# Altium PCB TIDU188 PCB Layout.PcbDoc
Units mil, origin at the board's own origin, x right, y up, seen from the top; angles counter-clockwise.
Board outline 3160 x 1390 mil, 4 copper layers (Top Layer, Ground, POWER, Bottom Layer), stack 90 mil thick; 74 components, 47 nets, 222 pads, 107 vias.
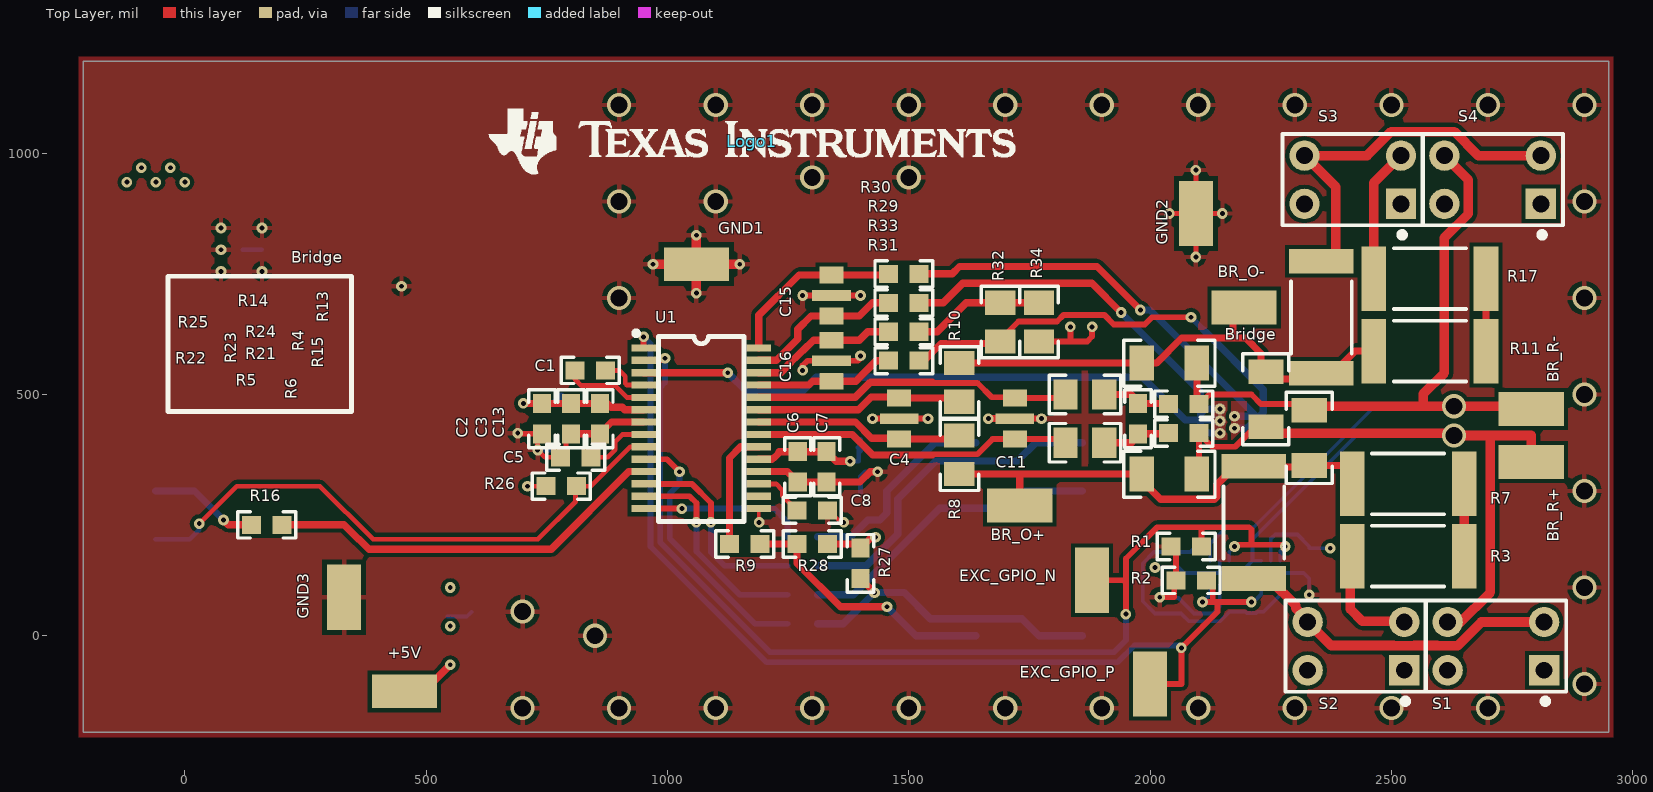
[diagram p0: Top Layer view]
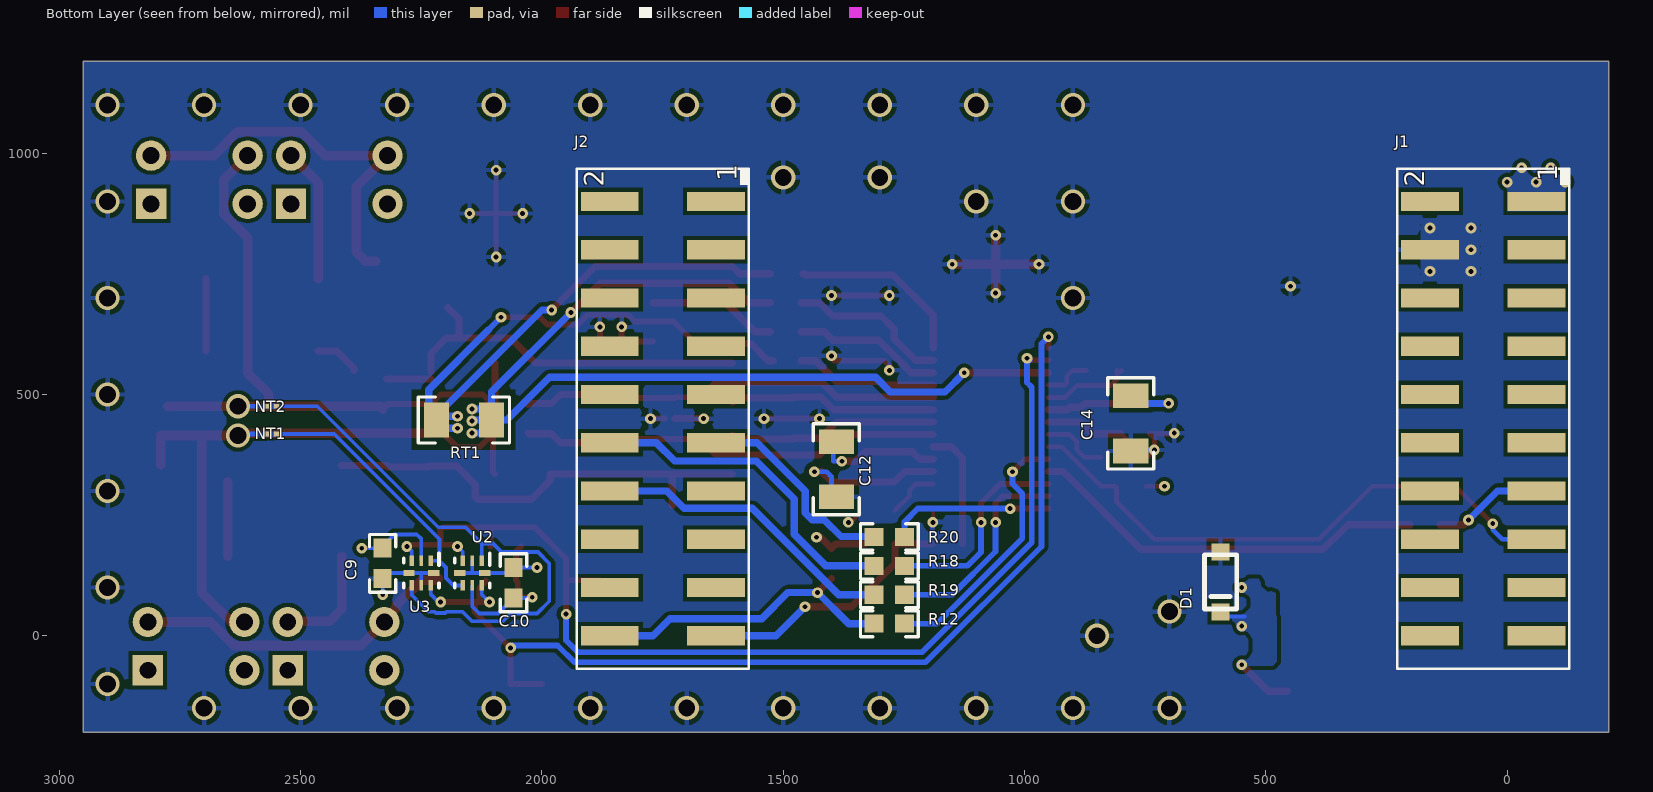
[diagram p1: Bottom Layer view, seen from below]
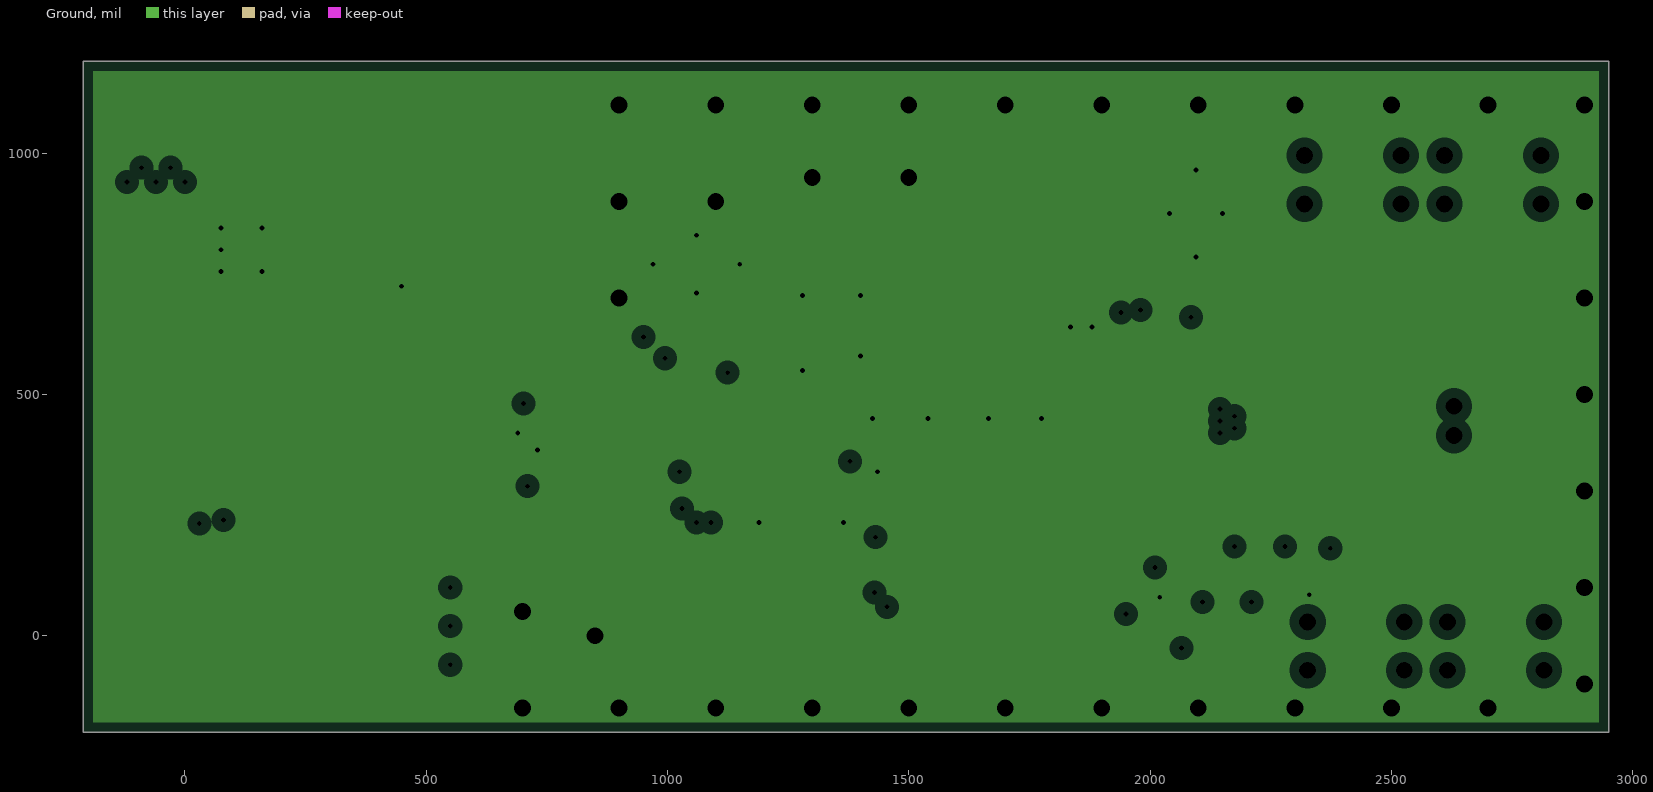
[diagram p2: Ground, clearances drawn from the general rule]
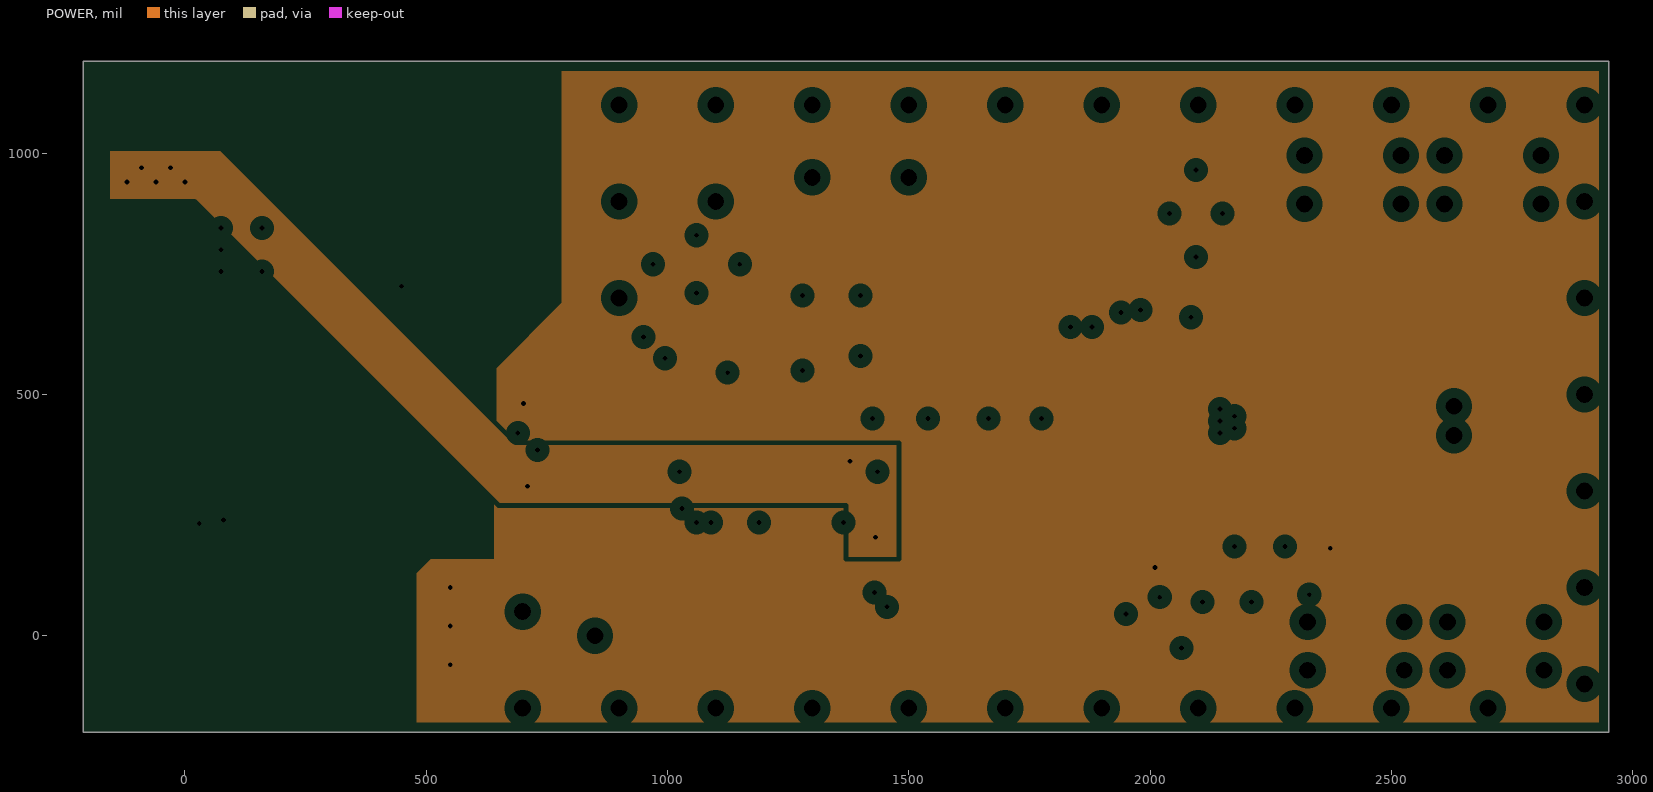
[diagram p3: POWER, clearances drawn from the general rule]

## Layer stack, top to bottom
Top Solder: solder mask 0.4, Solder Resist, Dk 3.5
Top Layer: signal copper 1.4
Dielectric1: core 59.2, FR-4, Dk 4.8
Ground: plane copper 1.4, net GND
Dielectric2: prepreg 12.6, FR-4, Dk 4.8
POWER: plane copper 1.4, net (Multiple Nets)
Dielectric3: core 12.6, FR-4, Dk 4.8
Bottom Layer: signal copper 1.4
Bottom Solder: solder mask 0.4, Solder Resist, Dk 3.5

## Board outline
-210,-200 2950,-200 2950,1190 -210,1190

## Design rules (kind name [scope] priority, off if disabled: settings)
AcuteAngle [All] p1: minimum=4.50000000000000E+0001 checktracksonly=FALSE
AssemblyTestPointUsage [All] p1: valid=2
Clearance Clearance_1 [InNet('NetJP1_1') OR InNet('GND') OR InNet('+3.3V') OR InNet('NetC16_2') OR InNet('NetC17_2') OR InNet('NetJ4_2') OR InNet('NetJ4_1') OR InNet('NetR21_1') OR InNet('NetR22_2') OR InNet('NetC32_2') OR InNet('-5V') OR InNet('+5V') OR InNet('NetJ1_7') OR InNet('NetJ1_6') OR InNet('NetJ1_13') OR InNet('NetJ1_11') OR InNet('NetR26_1') OR InNet('SDA') OR InNet('SCL') OR InNet('NetJ1_15') OR InNet('NetJ1_3') OR InNet('START') OR InNet('SCLK') OR InNet('DGND') OR NOT InAnyNet vs InNet('DGND')] p1 off: gap=10
Clearance GND_TIE [(InNet('GND') OR InNet('DGND'))] p2 off: gap=0
Clearance Clearance_BoardEdge_MountingHoles [OnCopper and InComponentClass('Mounting Holes') vs IsKeepOut] p3: gap=40
Clearance Clearance_BoardEdge_Poly [OnCopper and InPoly vs IsKeepOut] p4: gap=25
Clearance Clearance_BoardEdge [OnCopper and Not InComponentClass('Logo') and not InComponentClass('FiducialMark') and not InRegion(1000,500,4000,800) vs IsKeepOut] p5: gap=25
Clearance [All] p6: gap=8
ComponentClearance ComponentClearance_Logo [InComponentClass(Logo)] p1 off: gap=50 collisioncheckmode=3 verticalgap=10 showdistances=FALSE
ComponentClearance ComponentClearance_ScrewToNut [(HasFootprint('NY PMS 440 0025 PH')) vs (HasFootprint('Keystone_1902C'))] p2 off: gap=5 collisioncheckmode=3 verticalgap=10 showdistances=FALSE
ComponentClearance ComponentClearance_MountingHoles [InComponentClass('Mounting Holes')] p3 off: gap=250 collisioncheckmode=3 verticalgap=100000 showdistances=FALSE
ComponentClearance ComponentClearance_SmallPassives [HasFootprint('0201*') or HasFootprint('0402*') or HasFootprint('0508') or HasFootprint('0603*') or HasFootprint('0612') or HasFootprint('0805*') or HasFootprint('0815*') or HasFootprint('0830*') or HasFootprint('1206*') or HasFootprint('1210*') or HasFootprint('1808*') or HasFootprint('1812*') or HasFootprint('1825*') or HasFootprint('2010*') or HasFootprint('2220*') or HasFootprint('2225*') or HasFootprint('2512*') or HasFootprint('2728*') or HasFootprint('3518*') vs HasFootprint('0201*') or HasFootprint('0402*') or HasFootprint('0508') or HasFootprint('0603*') or HasFootprint('0612') or HasFootprint('0805*') or HasFootprint('0815*') or HasFootprint('0830*') or HasFootprint('1206*') or HasFootprint('1210*') or HasFootprint('1808*') or HasFootprint('1812*') or HasFootprint('1825*') or HasFootprint('2010*') or HasFootprint('2220*') or HasFootprint('2225*') or HasFootprint('2512*') or HasFootprint('2728*') or HasFootprint('3518*')] p4 off: gap=20 collisioncheckmode=3 verticalgap=10 showdistances=FALSE
ComponentClearance ComponentClearance_THtoSMT [IsThruComponent vs IsSMTComponent] p5 off: gap=100 collisioncheckmode=3 verticalgap=100000 showdistances=FALSE
ComponentClearance ComponentClearance_THtoTH [IsThruComponent vs IsThruComponent] p6 off: gap=118.11 collisioncheckmode=3 verticalgap=100000 showdistances=FALSE
ComponentClearance [All] p7 off: gap=40 collisioncheckmode=3 verticalgap=10 showdistances=FALSE
DiffPairsRouting [All] p1: maxlimit=100 minlimit=10 mostfreqgap=10 toplayer_minwidth=15 toplayer_maxwidth=15 toplayer_prefwidth=15 bottomlayer_minwidth=15 bottomlayer_maxwidth=15 bottomlayer_prefwidth=15 maxuncoupledlength=1000
FabricationTestPointUsage TestPointUsage [All] p1: valid=2 allowmultiple=FALSE
FabricationTestpoint Testpoint [All] p1: side=3 testpointundercomponent=TRUE minsize=40 maxsize=100 preferedsize=60 minholesize=0 maxholesize=40 preferedholesize=32 testpointgrid=1 allowsidetop=TRUE allowsidebottom=TRUE usegrid=TRUE gridtolerance=0.01
FanoutControl Fanout_LCC [IsLCC] p1: bgadir=Out bgaviamode=Centered fanoutstyle=Auto fanoutdirection=Alternating viagrid=1 // Fanout_LCC (Default Rule)
FanoutControl Fanout_BGA [IsBGA] p2: bgadir=Out bgaviamode=Centered fanoutstyle=Auto fanoutdirection=Alternating viagrid=1 // Fanout_BGA (Default Rule)
FanoutControl Fanout_Default [All] p4: bgadir=Out bgaviamode=Centered fanoutstyle=Auto fanoutdirection=Alternating viagrid=1 // Fanout_Default (Default Rule)
FanoutControl Fanout_Small [(CompPinCount < 5)] p5: bgadir=Out bgaviamode=Centered fanoutstyle=Auto fanoutdirection=OutThenIn viagrid=1 // Fanout_Small (Default Rule)
HoleSize [All] p1: absolutevalues=TRUE maxlimit=251 minlimit=8 maxpercent=80.000 minpercent=20.000
MatchedLengths [All] p1 off: tolerance=10 checknetsindiffpair=TRUE checkdiffpairvsdiffpair=TRUE checkothers=TRUE
MinimumAnnularRing [All] p1 off: minimumring=9
MinimumSolderMaskSliver MinimumSolderMaskSliver_Logo [InComponentClass('Logo') vs InComponentClass('Logo')] p1: minsoldermaskwidth=0.7
MinimumSolderMaskSliver [All] p2 off: minsoldermaskwidth=4
NetAntennae [All] p1: netantennaetolerance=-2
PlaneClearance [All] p1: clearance=20
PlaneConnect PlaneConnect_1 [InComponent('U301') or InNet('DVDD') or InComponent('U302')] p1: planeconnectstyle=Direct reliefexpansion=10 reliefentries=4 reliefconductorwidth=10 reliefairgap=6
PlaneConnect [All] p2: planeconnectstyle=Relief reliefexpansion=10 reliefentries=4 reliefconductorwidth=10 reliefairgap=10
PolygonConnect PowerPolygon [(ObjectKind = 'Poly') And ((Name = 'Boost_GND') Or (Name = 'Boost_OUT')Or (Name = 'Boost_IN')Or (Name = 'LDO_GND') Or (Name = 'LDO_IN') Or (Name = 'LDO_OUT') Or (Name = '+5V_Connector_B') Or (Name = '+5V_Connector_T')Or (Name = 'DVDD_PAD')Or (Name = 'GND_PAD')Or (Name = 'AINCOM_PL')Or (Name = 'NetR116_PL'))] p1: connectstyle=Direct reliefconductorwidth=10 reliefentries=2 polygonreliefangle="90 Angle" airgapwidth=10
PolygonConnect [All] p2: connectstyle=Relief reliefconductorwidth=10 reliefentries=4 polygonreliefangle="90 Angle" airgapwidth=10
RoutingVias [All] p1: holewidth=16 width=34 viastyle="Through Hole" minholewidth=8 minwidth=20 maxholewidth=40 maxwidth=65
SMDToCorner [All] p1: distance=30000
SilkToSilkClearance [All] p1: silktosilkclearance=5
SilkToSolderMaskClearance SilkscreenOverComponentPads [IsPad] p1 off: minsilkscreentomaskgap=5 clearancetoexposedcopper=TRUE
SolderMaskExpansion [All] p1: expansion=3
UnpouredPolygon [All] p1: allowunpoured=FALSE
Width [All] p1: maxlimit=100 minlimit=6 preferedwidth=10 checkconnectedcopper=TRUE
13 further rules are at their usual default settings.

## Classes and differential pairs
component class "TIDU188 Temp Sensor": C22 C23 R34 RT1

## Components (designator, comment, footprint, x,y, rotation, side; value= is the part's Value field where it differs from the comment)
+5V "5015" 5015 455,-115 r0 top
BR_O+ "5015" 5015 1730,270 r180 top
BR_O- "5015" 5015 2195,680 r180 top
BR_R+ "5015" 5015 2790,360 r180 top
BR_R- "5015" 5015 2790,470 r180 top
C1 "GRM188R71H472KA01D" 0603 840,550 r180 top
C2 "GRM185R61C105KE44D" 0603 740,450 r270 top
C3 "GRM188R71C104KA01D" 0603 800,450 r270 top
C4 "250X15W104MV4E" "X2Y 0805 (X15)" 1480,450 r180 top
C5 "GRM185R61C105KE44D" 0603 810,370 r180 top
C6 "GRM188R71C104KA01D" 0603 1270,350 r270 top
C7 "GRM185R61C105KE44D" 0603 1330,350 r270 top
C8 "GRM185R61C105KE44D" 0603 1300,260 r0 top
C9 "GRM185R61C105KE44D" 0603 2330,150 r90 bottom
C10 "GRM185R61C105KE44D" 0603 2058.82,110 r90 bottom
C11 "250X15W104MV4E" "X2Y 0805 (X15)" 1720,450 r180 top
C12 "C3216X7R1C106M" 1206 1390,345 r270 bottom
C13 "GRM188R71E103KA01D" 0603 860,450 r270 top
C14 "C3216X7R1C106M" 1206 780,440 r270 bottom
C15 "250X15W104MV4E" "X2Y 0805 (X15)" 1340,705 r180 top
C16 "250X15W104MV4E" "X2Y 0805 (X15)" 1340,570 r180 top
D1 "DDZ6V2B-7" SOD-123 593.86,111.66 r270 bottom
EXC_GPIO_N "5015" 5015 1880,115 r90 top
EXC_GPIO_P "5015" 5015 2000,-100 r90 top
GND1 "5015" 5015 1060,770 r180 top
GND2 "5015" 5015 2095,875 r270 top
GND3 "5015" 5015 330,80 r270 top
J1 "SSW-110-22-F-D-VS-K" CONN_SSW-110-22-F-D-VS-K 49.5,449.98 r90 bottom
J2 "SSW-110-22-F-D-VS-K" CONN_SSW-110-22-F-D-VS-K 1749.5,449.98 r90 bottom
Logo1 "Texas Instruments" TI_Horizontal_Overlay_Small 1175,1025 r0 top
NT1 "Net-Tie" Net-Tie_10mil 2560,417.91 r180 bottom net-tie
NT2 "Net-Tie" Net-Tie_10mil 2560,475.63 r0 bottom net-tie
R1 "ERJ-3GEYJ104V" 0603 2075,185 r180 top
R2 "ERJ-3GEYJ104V" 0603 2085,115 r180 top
R3 "804-2512" 2512 2535,165 r180 top
R4 "804-1206" 1206 2240,490 r270 top
R5 "804-1206" 1206 2040,335 r0 top
R6 "804-2512" 2512 2215,235 r270 top
R7 "804-2512" 2512 2535,315 r0 top
R8 "ERJ-3EKF47R0V" 0805_HV 1605,375 r90 top
R9 "ERJ-3EKF47R0V" 0603 1160,190 r0 top
R10 "ERJ-3EKF47R0V" 0805_HV 1605,525 r270 top
R11 "804-2512" 2512 2580,590 r180 top
R12 "ERJ-3EKF47R0V" 0603 1280,25 r0 bottom
R13 "804-2512" 2512 2355,660 r270 top
R14 "804-1206" 1206 2040,565 r180 top
R15 "804-1206" 1206 2330,410 r270 top
R16 "ERJ-3EKF47R0V" 0603 170,230 r180 top
R17 "804-2512" 2512 2580,740 r0 top
R18 "ERJ-3EKF47R0V" 0603 1280,145 r0 bottom
R19 "ERJ-3EKF47R0V" 0603 1280,85 r0 bottom
R20 "ERJ-3EKF47R0V" 0603 1280,205 r0 bottom
R21 "RG1608P-4990-B-T5" 0603 2070,420 r180 top
R22 "2-1879336-4" 0805_HV 1865,400 r180 top
R23 "RG1608P-9091-B-T5" 0603 1975,450 r270 top
R24 "RG1608P-4990-B-T5" 0603 2070,480 r180 top
R25 "2-1879336-4" 0805_HV 1865,500 r180 top
R26 "ERJ-3GEYJ104V" 0603 780,310 r0 top
R27 "ERJ-3GEYJ104V" 0603 1400,150 r270 top
R28 "ERJ-3GEYJ104V" 0603 1300,190 r0 top
R29 "RC0603FR-07499RL" 0603 1490,690 r180 top
R30 "RC0603FR-07499RL" 0603 1490,750 r180 top
R31 "RC0603FR-07499RL" 0603 1490,570 r180 top
R32 "RG2012P-102-B-T5" 0805_HV 1690,650 r270 top
R33 "RC0603FR-07499RL" 0603 1490,630 r180 top
R34 "RG2012P-102-B-T5" 0805_HV 1770,650 r90 top
RT1 "PTS120601B100RP100" 1206 2161.65,447.09 r180 bottom
S1 "200USP9T1A1M2RE" 200USP9xxxxM2 2716.65,-21.46 r180 top
S2 "200USP9T1A1M2RE" 200USP9xxxxM2 2426.65,-21.46 r180 top
S3 "200USP9T1A1M2RE" 200USP9xxxxM2 2420,945 r180 top
S4 "200USP9T1A1M2RE" 200USP9xxxxM2 2710,945 r180 top
U1 "ADS1263IPW" PW28 1070,430 r0 top
U2 "TS5A21366RSER" RSE-8 2144.41,130 r0 bottom
U3 "TS5A21366RSER" RSE-8 2250,130 r0 bottom

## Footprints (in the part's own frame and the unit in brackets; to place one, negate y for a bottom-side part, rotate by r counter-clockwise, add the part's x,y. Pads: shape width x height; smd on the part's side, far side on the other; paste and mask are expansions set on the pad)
200USP9xxxxM2 [mm] "E-SWITCH"
  rect 1.6x1.6 hole 0.889: 1(-2.54,1.27)
  round 1.6 hole 0.889: 3(2.54,1.27) 4(-2.54,-1.27) 6(2.54,-1.27)
  silkscreen extent -3.7,-2.4 3.7,3.05, body extent -3.5,-2.25 3.5,2.25, height 11.12
0603 [mm] "0603 from SM-752 data"
  rect 1x0.95 smd: 1(-0.8,0) 2(0.8,0)
  silkscreen extent -1.52,-0.69 1.52,0.69, body extent -0.87,-0.47 0.87,0.47, height 0.85
0805_HV [mil] "0805 with 30mil clearance between pads"
  rect 50x63 smd: 1(-40,0) 2(40,0)
  silkscreen extent -74,-40 74,40, body extent -43,-29 43,29, height 43
1206 [mm] "1206 from SM-752 data"
  rect 1.3x1.85 smd: 1(-1.45,0) 2(1.45,0)
  silkscreen extent -2.4,-1.21 2.4,1.21, body extent -1.7,-0.9 1.7,0.9, height 1.35
2512 [mm] "Chip Resistor, Body 6.3x3.2mm, IPC Medium Density"
  rect 1.3x3.4 smd: 1(-2.95,0) 2(2.95,0)
  silkscreen extent -1.9,-1.6 1.9,1.6, body extent -3.22,-1.67 3.22,1.67, height 0.71
5015 [mil]
  rect 135x70 smd: 1(0,0)
CONN_SSW-110-22-F-D-VS-K [mil]
  rect 40x120 smd: 1(450,-110) 2(450,110) 3(350,-110) 4(350,110) 5(250,-110) 6(250,110) 7(150,-110) 8(150,110) 9(50,-110) 10(50,110) 11(-50,-110) 12(-50,110) 13(-150,-110) 14(-150,110) 15(-250,-110) 16(-250,110) 17(-350,-110) 18(-350,110) 19(-450,-110) 20(-450,110)
  silkscreen extent -518,-178 518,178, body extent -510,-155 500,155, height 435
Net-Tie_10mil [mil] "10mil net tie, no solder mask opening, no solder paste"
  rect 10x10 smd paste-5 mask-5: 1(-10,0) 2(10,0)
  Top Layer region: -6,5 6,5 6,-5 -6,-5
PW28 [mil]
  rect 50.31x15 smd: 1(-119.34,166.4) 2(-119.34,140.8) 3(-119.34,115.2) 4(-119.34,89.6) 5(-119.34,64) 6(-119.34,38.4) 7(-119.34,12.8) 8(-119.34,-12.8) 9(-119.34,-38.4) 10(-119.34,-64) 11(-119.34,-89.6) 12(-119.34,-115.2) 13(-119.34,-140.8) 14(-119.34,-166.4) 15(119.34,-166.4) 16(119.34,-140.8) 17(119.34,-115.2) 18(119.34,-89.6) 19(119.34,-64) 20(119.34,-38.4) 21(119.34,-12.8) 22(119.34,12.8) 23(119.34,38.4) 24(119.34,64.1) 25(119.34,89.6) 26(119.34,115.2) 27(119.34,140.8) 28(119.34,166.5)
  silkscreen extent -140,-193 89,202
RSE-8 [mm]
  rect 0.25x0.55 smd: 1(-0.5,-0.65) 3(0.5,-0.65) 5(0.5,0.65) 7(-0.5,0.65)
  rect 0.2x0.55 smd: 2(0,-0.65) 6(0,0.65)
  rect 0.6x0.3 smd: 4(0.65,0) 8(-0.65,0)
  silkscreen extent -0.92,-1.02 0.92,0.77
SOD-123 [mm]
  rect 0.9x0.95 smd: 1(-1.575,0) 2(1.575,0)
  silkscreen extent -1.43,-0.85 1.43,0.85, body extent -1.43,-0.85 1.43,0.85, height 1.36
TI_Horizontal_Overlay_Small [mil]
  silkscreen extent -545,-68 545,67
"X2Y 0805 (X15)" [mil]
  rect 50x35 smd: A(0,42.5) B(0,-42.5)
  rect 80x22 smd: G(0,0)

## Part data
+5V BR_O+ BR_O- BR_R+ BR_R- EXC_GPIO_N EXC_GPIO_P GND1 GND2 GND3: library part "Test Point SMT", "TEST POINT, MINIATURE, SMT"
C1: library part Cap_small, "CAP, CERM, 4700pF, 50V, +/-10%, X7R, 0603"
C2 C5 C7 C8 C9 C10: library part Cap_small, "CAP, CERM, 1uF, 16V, +/-10%, X5R, 0603"
C3 C6: library part Cap_small, "CAP, CERM, 0.1uF, 16V, +/-10%, X7R, 0603"
C4 C11 C15 C16: library part CAP_X2Y, "CAP, CERM X2Y, 100 nF, 25V, X7R, +/-20%, 0805"
C12: library part Cap_small, "CAP, CERM, 10 uF, 16V, X7R +/-20%, 1206"
C13: "CAP, CERM, 0.01uF, 25V, +/-10%, X7R, 0603"
C14: library part Capacitor, "CAP, CERM, 10 uF, 16V,  X7R +/-20%, 1206"
D1: library part "Zener Diode", "DIODE, ZENER, 6.2V, 500mW, SOD-123"
J1 J2: "Connector, Receptacle, 100mil, 10x2, Gold plated, SMD"
Logo1: library part TI_Logo, "Texas Instrument Corporate Signature"
NT1 NT2: "Single point connection between nets."
R1 R2 R26: library part Resistor_small, "RES, 100k Ohm, 5%, 1/10W, 0603"
R3 R6 R11 R13: library part Resistor_small, "RES, 87.325k Ohm, 0.01%, 0.75W, 2512"
R4 R5 R14 R15: library part Resistor_small, "RES, 350 ohm, 0.25%, 0.3W, 1206"
R7: library part Resistor_small, "RES, 87.5 kohm, 0.5%, 0.75W, 2512"
R8 R9 R10 R12 R16 R18 R19 R20 R22 R25: library part Resistor, "RES, 47 Ohm, 1%, 1/10W, 0603"
R17: library part Resistor_small, "RES, 87.5k Ohm, 0.5%, 0.75W, 2512"
R21 R24: "RES, 499 ohm, 0.1%, 0.1W, 0603"
R23: "RES, 9.09k ohm, 0.1%, 0.1W, 0603"
R27 R28: library part Resistor, "RES, 100k Ohm, 5%, 1/10W, 0603"
R29 R30 R31 R33: "RES, 499 ohm, 1%, 0.1W, 0603"
R32 R34: "RES, 1.00k ohm, 0.1%, 0.125W, 0805"
RT1: "Temperature Sensor, 100 ohm, 1%, 1206"
S1 S2 S3 S4: "Switch, Toggle, SPST, 1Pos, TH"
U1: library part ADS126XPW, "IC, 32-bit, 38kSPS ADC"
U2 U3: library part TS5A21366RSE, "IC, Single-Channel 10 Ohms SPDT Analog Switch with enable"

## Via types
v1: diameter 22, hole 10, Top Layer to Bottom Layer, 70 vias
v2: diameter 50, hole 35, Top Layer to Bottom Layer, 37 vias

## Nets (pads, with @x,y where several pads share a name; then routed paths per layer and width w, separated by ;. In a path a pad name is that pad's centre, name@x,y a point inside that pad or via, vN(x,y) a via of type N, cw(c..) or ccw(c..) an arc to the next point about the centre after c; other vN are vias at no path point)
\CS: J2.20 R12.2 R27.2 | length 652.8
  Top Layer w15: R27.2 v1(1428.96,89.54)
  Bottom Layer w15: R12.2 1364.42,25 v1(1428.96,89.54) 1490.46,89.54 1544.52,35.48 1734.52,35.48 1770.02,-0.02 J2.20
\DRDY: J2.11 R20.2 | length 435.5
  Bottom Layer w15: R20.2 1312.08,205.58 1380.58,205.58 1415,240 1440,240 1454.42,254.42 1454.42,300.04 1554.36,399.98 J2.11
\RESET/PWDN: J2.19 R9.2 R28.1 | length 550.1
  Top Layer w15: R9.2 R28.1 1268.5,150 1358.5,60 v1(1455,60)
  Bottom Layer w15: v1(1455,60) 1515.02,-0.02 J2.19
AIN0: C11.A R22.2 U1.21 | length 683
  Top Layer w12: 1550,376 1642.3,376 1673.8,407.5 1725,407.5 1832.5,407.5 R22.2@1840,400
  Top Layer w15: U1.21 1382.8,417.2 1425.5,374.5 1548.5,374.5
AIN1: C4.A R8.2 U1.22 | length 432.6
  Top Layer w15: U1.22 1389.73,442.8 1423.03,409.5 C4.A@1480,409.5 ; C4.A 1597.5,407.5 R8.2
AIN2: C4.B R10.2 U1.23 | length 429.8
  Top Layer w15: U1.23 1395.93,468.4 1422.47,494.95 C4.B@1480,494.95 ; C4.B 1597.5,492.5 R10.2
AIN3: C11.B R25.2 U1.24 | length 677.7
  Top Layer w12: 1550,524 1642.3,524 1672.2,494.1 C11.B@1725,494.1 ; C11.B@1725,492.5 1832.5,492.5 R25.2@1840,500
  Top Layer w15: U1.24 1389.1,494.1 1420.5,525.5 1548.5,525.5
AIN4: C16.A R31.2 U1.25 | length 295
  Top Layer w15: U1.25 1292.67,519.6 1300.57,527.5 C16.A 1389.97,527.5 1432.47,570 R31.2@1463.5,570
AIN5: C16.B R33.2 U1.26 | length 309.9
  Top Layer w15: U1.26 1235.2,545.2 1249.5,559.5 1249.5,560.56 1264.44,575.5 1265.09,575.5 1281.09,591.5 1281.5,591.5 1302.5,612.5 C16.B 1397.5,612.5 1415,630 R33.2@1463.5,630
AIN6: C15.A R29.2 U1.27 | length 335.3
  Top Layer w15: U1.27 1225.8,570.8 1270,615 1270,635 1297.5,662.5 C15.A 1397.5,662.5 1425,690 R29.2 R29.2@1463.5,690
AIN7: C15.B R30.2 U1.28 | length 372.5
  Top Layer w15: U1.28 1189.34,664.34 1272.5,747.5 C15.B 1456,747.5 R30.2
AINCOM: R29.1 RT1.2 U1.3 | length 2110.7
  Top Layer w15: U1.3 v1(1124.8,545.2) ; R29.1@1526.5,690 1571.5,690 1612,730.5 1879.5,730.5 v1(1940,670)
  Bottom Layer w15: v1(1124.8,545.2) 1165,505 1278.07,505 1308.56,535.48 1984.52,535.48 2072.91,447.09 RT1.2 ; v1(1940,670) 2104.57,505.43 RT1.2@2104.57,459.57 ; v1(2145,420) 2120,420 2104.57,435.43 RT1.2 ; v1(2145,445) 2142.91,447.09 RT1.2 ; v1(2145,470) 2115,470 RT1.2@2104.57,459.57 ; RT1.2 RT1.2@2104.57,459.57
AVDD: +5V.1 C2.1 C3.1 C9.2 C10.2 C13.1 C14.1 D1.2 U1.6 U2.2 U2.4 U2.8 U3.2 | length 887.8
  Top Layer w15: +5V.1 495,-115 v1(550,-60) ; v1(701.5,481.5) C2.1 C3.1 C13.1 875.21,481.5 883.21,473.5 906.5,473.5 911.6,468.4 U1.6
  Bottom Layer w8: 544.51,40 584.2,40 D1.2 ; v1(2010.31,141.5) C10.2 2070.31,130 U2.8 2146.05,130 ; U2.2 2144.41,131.65 2146.05,130 ; U2.4 2146.05,130 ; U3.2 2250,200.51 2259.49,210 2305.25,210 2330,185.25 C9.2 v1(2373.5,181.5)
  Bottom Layer w15: v1(701.5,481.5) 764.41,481.5 C14.1
  other v1: 550,20 550,100
DIN: J2.12 R18.2 | length 696.4
  Bottom Layer w15: R18.2 1411.94,145 1477.42,210.47 1477.42,283.44 1555.96,361.98 1725.05,361.98 1763.05,399.98 J2.12
DOUT/\D\R\D\Y: J2.14 R19.2 | length 637.1
  Bottom Layer w15: R19.2 1385,85 1564.48,264.48 1705.92,264.48 1741.42,299.98 J2.14
DVDD: C6.1 C7.1 C12.1 J1.1 R26.1 R27.1 R28.2 U1.19 | length 424.2
  Top Layer w10: v1(710,310) R26.1
  Top Layer w15: U1.19 1216,366 1218.6,368.6 1220.92,368.6 1229.99,377.68 1229.99,380 1231.5,381.5 C6.1 C7.1 1350,361.5 v1(1378.5,361.5) ; R28.2 1391.5,190 R27.1 v1@1422.83,204.32
  Bottom Layer w10: v1(1378.5,361.5) 1396.5,361.5 C12.1@1396.5,379.49 ; C12.1@1395,390 1396.5,388.5 C12.1@1396.5,379.49 ; C12.1@1400,407.09 1400,382.99 C12.1@1396.5,379.49
  other v1: 1431.03,204.32 -120,940 -60,940 0,940 -90,970 -30,970
EXC0: NT1.2 U2.5 U3.1 | length 572.3
  Bottom Layer w8: U2.5 2182.95,104.41 2198.6,120.06 2198.6,141.7 2212.48,155.59 ; U3.1 2212.48,155.59 ; NT1.2 2430.46,417.91 2212.48,199.94 2212.48,155.59
EXC1: NT2.1 U2.1 U3.5 | length 1161.1
  Bottom Layer w8: U2.1 2124.72,191.4 ; U3.5 2269.68,83.95 2235.42,49.68 2222.21,49.68 2219.53,47 2200.47,47 2197.79,49.68 2164.68,49.68 2145,30 2080.94,30 2064.43,46.5 2010,46.5 1985,71.5 1985,150 2008.5,173.5 2083.5,173.5 2101.4,191.4 2124.72,191.4 ; NT2.1 2465.54,475.63 2214.92,225 2158.32,225 2124.72,191.4
GND: C2.2 C3.2 C4.G C5.2 C6.2 C7.2 C8.2 C9.1 C10.1 C11.G C12.2 C13.2 C14.2 C15.G C16.G D1.1 GND1.1 GND2.1 GND3.1 J1.4 R1.2 R2.2 R34.1 U1.7 U1.15 U1.18 U2.6 U3.4 U3.6 U3.8 | length 2588.7
  Top Layer w8: U1.15 1189.34,240.66 1190,240 v1(1190,235) ; C8.2@1340,255 1360,235 v1(1365,235)
  Top Layer w10: C2.2 731.04,409.54 v1(731.04,385) 746.04,370 C5.2 790,381.5 790,408.5 C3.2 ; v1(2040,875) GND2.1 ; v1(2095,785) GND2.1 ; v1(2095,965) GND2.1 ; v1(2150,875) GND2.1
  Top Layer w12: v1@691.5,418.5 C2.2 ; v1@1275,550 1280,555 1280,560 1290,570 C16.G 1395,570 1405,580 v1(1400,580) ; v1(1280,705) C15.G v1(1400,705) ; v1@1420,450 C4.G v1(1540,450) ; C11.G@1745,450 v1(1775,450) ; R34.1 1835,610 ; v1@1835,630 1835,610 ; v1@1885,640 1880,635 v1(1880,640) 1880,620 1870,610 1847,610 1835,610 ; v1(2020,80) 2050,80 2050,111.5 R2.2 2053.5,175 R1.2
  Top Layer w15: C3.2 C13.2 884.3,442.8 U1.7 ; U1.18 1248.1,340.4 C6.2 C7.2 1398.5,318.5 1420,340 v1(1435.43,340) ; v1(1665,450) C11.G@1725,450
  Top Layer w20: v1(970,770) GND1.1 ; v1(1060,710) GND1.1 ; v1(1060,830) GND1.1 ; v1(1150,770) GND1.1
  Bottom Layer w8: v1@1189.34,240.66 1190,240 v1(1190,235) ; v1@2021.5,78.5 C10.1 2091.32,46 2130.07,46 2144.41,60.34 U2.6 ; U3.8 2250,130 ; U3.6 2250,130 ; v1(2330,85) C9.1 2318.5,130 U3.4 2250,130
  Bottom Layer w10: J1.4@120,799.98 J1.4 ; v1(731.04,385) 777.91,385 C14.2 ; C12.2@1400,292.91 1400,330 1410,340 v1(1435.43,340)
  other v1: 690,420 1425,450 1280,550 1835,640 448.96,724.18 74.98,755.02 159.98,755.02 75,800 75,844.98 159.98,845.02
  other v2: 700,-150 900,-150 1100,-150 1300,-150 1500,-150 1700,-150 1900,-150 2100,-150 2300,-150 2500,-150 2700,-150 2900,-100 850,0 700,50 2900,100 2900,300 2900,500 900,700 2900,700 900,900 1100,900 2900,900 1300,950 1500,950 900,1100 1100,1100 1300,1100 1500,1100 1700,1100 1900,1100 2100,1100 2300,1100 2500,1100 2700,1100 2900,1100
HS_EXC0: EXC_GPIO_P.1 R2.1 U1.1 U2.7 U3.7 | length 2193.8
  Top Layer w12: U1.1 v1(950.66,619.34) ; EXC_GPIO_P.1 2065,-100 v1(2065,-25) 2110,20 2140,50 2140,70 ; v1(2108.82,70) 2140,70 ; R2.1 2116.5,112.64 2130,99.13 2130,70 ; v1(2210,70) 2210,75 2205,70 2140,70
  Bottom Layer w8: v1(2108.82,70) 2124.72,85.91 U2.7 ; v1@2210,75 v1(2210,70) 2215,70 2230.31,85.31 U3.7
  Bottom Layer w12: v1(950.66,619.34) 965,605 965,185 1205,-55 1932.61,-55 1967.61,-20 v1@2060,-20 ; v1(2065,-25) v1@2065,-20
HS_EXC1: EXC_GPIO_N.1 R1.1 U1.2 U2.3 U3.3 | length 2261.1
  Top Layer w12: U1.2 v1@990,570.8 ; EXC_GPIO_N.1 1945,115 ; v1(1950,45) 1950,110 1945,115 ; R1.1 2106.5,223.5 2105,225 ; v1(2175,185) 2178.5,188.5 2210,188.5 ; v1(2280,185) 2276.5,188.5 2210,188.5 ; 1945,115 1950,115 1950,160 2015,225 2105,225 ; 2105,225 2205,225 2210,220 2210,188.5
  Bottom Layer w8: U2.3 2164.09,174.09 v1(2175,185) ; U3.3 2269.68,174.68 v1(2280,185)
  Bottom Layer w12: v1@990,570.8 995,565.8 995,525 985,515 985,193.28 1212.3,-34.02 1925.3,-34.02 1950,-9.32 v1@1950,35.68
  other v1: 995,575
NetBR_O+_1: BR_O+.1 R5.1 R6.1 R7.1 R8.1 R15.2 | length 948.1
  Top Layer w15: R8.1 1730,335 ; BR_O+.1 1730,335 ; R6.1@2235,350 R15.2@2320,350 ; R6.1@2235,352.09 2177.09,352.09 2138.18,313.18 2138.18,288.18 2133.08,283.08 2021.92,283.08 1982.91,322.09 R5.1 1795,335 1730,335 ; R15.2@2320,352.91 R7.1@2415.83,352.91
NetBR_O-_1: BR_O-.1 R4.1 R10.1 R11.2 R13.2 R14.2 | length 955.9
  Top Layer w15: R10.1 R14.2 2013.16,565 2065.08,616.92 2171.92,616.92 ; BR_O-.1 2171.92,656.92 2171.92,616.92 ; R4.1@2230,532.09 R13.2@2322.28,532.09 ; R4.1@2230,547.09 2230,585 2198.08,616.92 2171.92,616.92 ; R13.2@2390,550 2390,555 2425,590 R11.2
NetC1_1: C1.1 U1.4 | length 100.3
  Top Layer w10: C1.1 900,550 912.51,537.5 912.51,522.95 915.86,519.6 U1.4
NetC1_2: C1.2 U1.5 | length 178.3
  Top Layer w10: C1.2@798.5,550 C1.2@800,548.5 ; C1.2 808.5,531.5 821.7,518.3 891.7,518.3 916,494 U1.5
NetC8_1: C8.1 U1.17 | length 108.6
  Top Layer w10: U1.17 1225.2,314.8 1238.3,301.7 1238.3,290.2 C8.1
NetR3_1: R3.1 R7.2 | length 153.9
  Top Layer w20: R3.1 R7.2@2651.14,318.86
NetR3_2: R3.2 S2.4 | length 232.6
  Top Layer w20: R3.2@2415,165 2415,55 2440,30 2525.2,30 S2.4
NetR6_2: R6.2 S1.4 S2.6 | length 686.6
  Top Layer w20: R6.2 2218.86,115 2250,115 2302,63 2302,57 2326.65,32.35 S2.6 2375.2,-20 2505.2,-20 2506.15,-20.95 2547.16,-20.95 2548.11,-20 2595.2,-20 2596.15,-20.95 2637.16,-20.95 2686.65,28.54 S1.4
NetR9_1: R9.1 U1.20 | length 248.9
  Top Layer w15: R9.1 1128.5,368.5 1151.6,391.6 U1.20
NetR11_1: R11.1 R17.2 | length 150
  Top Layer w15: R11.1 R17.2
NetR12_1: R12.1 U1.10 | length 548.5
  Top Layer w12: U1.10 999,366 v1(1025,340)
  Bottom Layer w12: v1(1025,340) 1025,315 1005,295 1005,201.57 1181.57,25 R12.1
NetR13_1: R13.1 S3.6 S4.4 | length 805.7
  Top Layer w20: R13.1@2345,776.14 2366.14,776.14 2385,795 2385,930 S3.6 2450,995 2499.5,1044.5 2630.5,1044.5 2680,995 S4.4
NetR16_1: R16.1 U1.11 | length 836.7
  Top Layer w15: R16.1 330,230 360,200 361.01,200 381.51,179.5 739.99,179.5 740.04,179.56 759.16,179.56 920,340.4 U1.11
NetR17_1: R17.1 S3.4 | length 278.3
  Top Layer w20: R17.1 2463.86,938.86 S3.4
NetR18_1: R18.1 U1.12 | length 427.8
  Top Layer w12: U1.12 1050.2,314.8 1090,275 v1(1090,235)
  Bottom Layer w12: v1(1090,235) 1090,173.14 1118.14,145 R18.1
NetR19_1: R19.1 U1.13 | length 441.1
  Top Layer w12: U1.13 1045.8,289.2 1060,275 v1(1060,235)
  Bottom Layer w12: v1(1060,235) 1060,174.85 1149.85,85 R19.1
NetR20_1: R20.1 U1.14 | length 340.6
  Top Layer w12: U1.14 v1(1030,263.6)
  Bottom Layer w12: v1(1030,263.6) 1221.4,263.6 1248.5,236.5 R20.1
NetR21_2: R21.2 R22.1 R23.2 | length 116.8
  Top Layer w15: R22.1@1920,400 1961.5,400 1980,418.5 2027.01,418.5 R21.2@2028.5,420
NetR23_1: R23.1 R24.2 R25.1 | length 116.8
  Top Layer w15: R25.1@1920,500 1961.5,500 1980,481.5 2027.01,481.5 R24.2@2028.5,480
NetR30_1: R30.1 R31.1 R32.2 RT1.1 | length 1822.4
  Top Layer w12: R32.2@1680.5,605.5 1681.8,605.5 1727.3,651 1807.3,651 1821.3,665 1905,665 1925,645 1988.94,645 2003.94,660 v1(2085,660)
  Top Layer w15: R31.1@1520,570 R31.1 1531.58,570 1567.08,605.5 R32.2@1680.5,605.5 ; R30.1@1526.5,750 1590,750 1605,765 1890,765 v1(1980,675)
  Bottom Layer w12: v1(2085,660) 2110,635 2110,634.57
  Bottom Layer w15: v1(1980,675) 2000,675 RT1.1@2217.28,457.72 ; 2110,634.57 2234.54,510.02 2234.54,462.89 RT1.1 ; v1(2175,430) 2201.65,430 RT1.1 ; v1(2175,455) 2210.83,455 RT1.1
NetR32_1: R32.1 R33.1 R34.2 | length 268.4
  Top Layer w15: R33.1@1526.5,630 1559.05,630 1619.05,690 R32.1 R34.2
REF0: BR_R+.1 NT1.1 R4.2 R5.2 R21.1 S1.6 | length 1364.8
  Top Layer w12: R5.2 2101.5,339.41 R21.1 2101.5,418.5 2128.32,391.68 2176.68,391.68 2217.91,432.91 R4.2@2225,432.91
  Top Layer w20: R4.2@2225,430 2235,420 2625,420 v2(2630,415) 2790,415 BR_R+.1 BR_R+.1@2790,355 ; S1.6@2615,25 2640,25 2705,90 2705,415
  Bottom Layer w10: NT1.1 v2@2621.65,417.91
REF1: BR_R-.1 NT2.2 R14.1 R15.1 R24.1 S4.6 | length 1405
  Top Layer w12: R24.1 2102.78,480 2122.78,500 2210,500 2230,480 R15.1@2320,480 ; R15.1@2320,477.09 R15.1@2325,477.09
  Top Layer w15: R14.1 2097.09,484.41 R24.1 ; R15.1@2325,475 2325.63,475.63 R15.1@2330,475.63
  Top Layer w20: R15.1@2330,470 2335.63,475.63 v2(2630,475.63) 2774.37,475.63 BR_R-.1@2775,475 ; 2566,477.09 2566,501 2610,545 2610,825 2659.5,874.5 2659.5,944.5 2610,993.99 S4.6
  Bottom Layer w10: NT2.2 v2@2618.11,475.63
REFOUT: C5.1 U1.8 | length 138.1
  Top Layer w10: C5.1 876.04,370 891.7,385.66 891.7,401.7 907.2,417.2 U1.8
SCLK: J1.13 R16.2 | length 228
  Top Layer w15: v1(80,240) 90,230 R16.2
  Bottom Layer w15: J1.13 20.02,299.98 v1(80,240)
START: J1.15 R26.2 U1.9 | length 1206.5
  Top Layer w10: v1(30,232.43) 107.57,310 280,310 390,200 731.5,200 809.8,278.3 809.8,308.3 R26.2 841.5,310 923.1,391.6 U1.9
  Bottom Layer w10: J1.15 9.98,199.98 30,220 v1(30,232.43)
pads on no net: J1.2 J1.3 J1.5 J1.6 J1.7 J1.8 J1.9 J1.10 J1.11 J1.12 J1.14 J1.16 J1.17 J1.18 J1.19 J1.20 J2.1 J2.2 J2.3 J2.4 J2.5 J2.6 J2.7 J2.8 J2.9 J2.10 J2.13 J2.15 J2.16 J2.17 J2.18 S1.1 S1.3 S2.1 S2.3 S3.1 S3.3 S4.1 S4.3 U1.16

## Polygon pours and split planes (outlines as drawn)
GND on Bottom Layer "GND_PAD" (solid, pour order 21): 55.6,735 179.38,735 179.38,865 55.6,865
GND on Bottom Layer "LDO_GND" (solid, remove dead copper, pour order 15): 416.38,471.63 426.38,461.63 426.38,391.63 406.38,391.63 396.38,381.63 396.38,301.63 606.38,301.63 606.38,221.63 396.38,221.63 396.38,141.63 423.07,115.18 446.38,115.18 446.38,56.63 416.38,56.63 406.38,46.63 406.38,-80 290,-80 290,531.63 416.38,531.63
AVDD on Bottom Layer "LDO_OUT" (solid, pour order 20): 477.45,126.63 570,126.63 570,-80 466.38,-80 466.38,-63.37 477.45,-53.37
DVDD on Bottom Layer "DVDD_PAD" (solid, pour order 22): -140,880 -120,860 0,860 20,880 20,970 0,990 -120,990 -140,970 -140,880
GND on Bottom Layer "BOT_GND" (solid, remove dead copper, pour order 19): -210,1190 -210,-200 2950,-200 2950,1190 -210,1190
NetR30_1 on Top Layer "NetR116_PL" (solid, pour order 16): 2160,485 2160,405 2180,405 2200,425 2200,490 2160,490 2160,485
AINCOM on Top Layer "AINCOM_PL" (solid, pour order 13): 2125,485 2125,405 2130,400 2160,400 2160,490 2130,490 2125,490 2125,485
GND on Top Layer "TOP_GND" (solid, remove dead copper, pour order 17): -220,1200 -220,-210 2960,-210 2960,1200 -220,1200
GND on Ground (split plane): 2929.9,-179.9 -189.9,-179.9 -189.9,1169.9 2929.9,1169.9
AVDD on POWER (split plane): 2929.9,-179.9 479.65,-179.9 479.65,129.65 510,160 640,160 640,272.79 646.4,266.4 648.05,265.29 650,264.9 1364.9,264.9 1364.9,158.45 1365.29,156.5 1366.4,154.85 1368.05,153.74 1370,153.35 1480,153.35 1481.95,153.74 1483.6,154.85 1484.71,156.5 1485.1,158.45 1485.1,240 1485.1,270 1485.1,400 1484.71,401.95 1483.6,403.6 1481.95,404.71 1480,405.1 686.89,405.1 644.77,447.21 644.77,554.77 780,690 780,1169.9 2929.9,1169.9
DVDD on POWER (split plane): 681.17,396.4 682.82,395.29 684.77,394.9 1474.9,394.9 1474.9,270 1474.9,240 1474.9,163.55 1375.1,163.55 1375.1,270 1374.71,271.95 1373.6,273.6 1371.95,274.71 1370,275.1 652.11,275.1 23.6,903.6 21.95,904.71 20,905.1 -154.9,905.1 -154.9,1004.9 72.66,1004.9

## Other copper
Bottom Layer:
  pour cut-out: 2055,510 2055,385 2270,385 2270,510
POWER (plane layer: these items are gaps in the copper):
  region: 644.77,440 644.77,554.77 780,690 780,1190 -210,1190 -210,900 -160,900 -160,1010 74.77,1010
  region: -210,900 20,900 640,280 640,160 510,160 479.65,129.65 479.65,-199.65 480,-200 -210,-200
  lines w10: -160,900 20,900 650,270 1370,270 1370,158.45 1480,158.45 1480,240 1480,270 1480,400 684.77,400 74.77,1010 -160,1010 -160,900

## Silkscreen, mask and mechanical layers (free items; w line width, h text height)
Top Overlay:
  lines w10: -35,465 -35,685 -35,745 345,745 345,465 -35,465
  text "Bridge" at 220,765 h40
  text "Bridge" at 2155,605 h40
M9 Title Sheet:
  drawing of 57 lines, arcs and shapes, not listed
  text "1" at -670.16,6171.68 h70
  text "2" at 1825.51,6171.68 h70
  text "3" at 4314.85,6171.68 h70
  text "4" at 6821.52,6171.68 h70
  text "5" at 9320.51,6171.68 h70
  text "6" at 11825.51,6171.68 h70
  text "A" at -1826.49,5028.68 h70
  text "A" at 12973.51,5028.68 h70
  text "B" at -1826.49,2648.68 h70
  text "B" at 12973.51,2648.68 h70
  text "C" at -1826.49,273.68 h70
  text "C" at 12973.51,273.68 h70
  text "PROJECT TITLE:" at 9933.51,-1587.32 h45
  text ".PRJ_Title" at 9983.51,-1720.65 h70
  text "DESIGNED FOR:" at 9933.51,-1888.32 h45
  text ".PRJ_Customer" at 9983.51,-2028.32 h70
  text "D" at -1826.49,-2096.32 h70
  text "D" at 12973.51,-2096.32 h70
  text "FILE NAME:" at 9933.51,-2188.32 h45
  text ".PCB_File_Name_No_Path" at 9983.51,-2308.32 h70
  text "Texas Instruments (TI) and/or its licensors do not warrant the accuracy or completeness of this specification" at 4964.01,-2470.16 h45
  text "ENGINEER:" at 9933.51,-2478.32 h45
  text "LAYOUT BY:" at 11438.51,-2478.32 h45
  text "or any information contained therein. TI and/or its licensors do not warrant that this design will meet" at 4919.02,-2582.82 h45
  text ".PRJ_Engineer" at 9983.51,-2633.31 h70
  text ".PCB_Layout" at 11489.01,-2633.31 h70
  text "the specifications, will be suitable for your application or fit for any particular purpose, or will operate in" at 4919.02,-2695.49 h45
  text ".Layer_Name" at -832.99,-2723.31 h60
  text "ALTIUM DESIGNER VERSION:" at 11438.51,-2788.32 h45
  text "an implementation. TI and/or its licensors do not warrant that the design is production worthy. You should" at 4919.02,-2808.16 h45
  text "completely validate and test your design implementation to confirm the system functionality for your application." at 4964.01,-2920.82 h45
  text ".print_Scale" at 9983.51,-2921.65 h70
  text ".Application_BuildNumber" at 11489.01,-2921.65 h70
  text "1" at -670.16,-3128.32 h70
  text "2" at 1825.51,-3128.32 h70
  text "3" at 4314.85,-3128.32 h70
  text "4" at 6821.52,-3128.32 h70
  text "5" at 9320.51,-3128.32 h70
  text "6" at 11825.51,-3128.32 h70
M10 Fab Notes:
  drawing of 185 lines, arcs and shapes, not listed
  text "DESIGN INFORMATION" at 10971.02,4045.18 h60
  text "MIN. TRACK WIDTH:" at 10326.46,3865.18 h60
  text "8" at 11422.71,3865.18 h60
  text "MIL" at 11577.46,3865.18 h60
  text "MIN. CLEARANCE:" at 10326.46,3733.18 h60
  text "0.2" at 11362.71,3733.18 h60
  text "mm" at 11577.46,3733.18 h60
  text "MIN. VIA PAD SIZE:" at 10326.46,3601.18 h60
  text "24" at 11392.72,3601.18 h60
  text "MIL" at 11577.46,3601.18 h60
  text "0.05mm (2MIL)" at 11021.46,3459.47 h60
  text "MINIMUM ANNULAR RING" at 9997.23,3455.18 h60
  text "EXTERNAL" at 11729.46,3455.18 h60
  text "PER" at 10197.23,3337.18 h60
  text "IPC-D-275 CLASS 2 LEVEL C" at 10417.23,3337.18 h60
  text "MIL, HOLES" at 11905.46,3224.89 h60
  text "+/-" at 11513.01,3224.18 h60
  text "+/-" at 12367.01,3224.18 h60
  text "REGISTRATION TOLERANCES:" at 9997.23,3219.18 h60
  text "METAL" at 11197.01,3219.18 h60
  text "5" at 11773.21,3219.18 h60
  text "3" at 12606.21,3219.18 h60
  text "MIL" at 12722.46,3219.18 h60
  text "MATERIAL:" at 9922.46,3009.72 h60
  text "FR-4 High Tg" at 10908.91,2869.39 h60
  text "FR-408" at 10343.47,2860.82 h60
  text "X" at 10755.47,2860.82 h60
  text "OTHER" at 11831.46,2860.82 h60
  text "62 MIL (1.6mm) +/-10%" at 10663.57,2698.1 h60
  text "THICKNESS:" at 9997.23,2693.82 h60
  text "X" at 10535.4,2693.82 h60
  text "OTHER" at 11948.47,2693.82 h60
  text "TOLERANCE:" at 9997.23,2535.82 h60
  text "X" at 10836.54,2535.82 h60
  text "ANSI IPC-6012 TYPE 3 CLASS 2" at 11023.48,2535.82 h60
  text "OTHER +/-" at 11023.46,2379.82 h60
  text "BOW & TWIST:" at 9997.23,2222.82 h60
  text "X" at 10836.54,2222.82 h60
  text "ANSI IPC-6012 TYPE 3 CLASS 2" at 11023.48,2222.82 h60
  text "OTHER +/-" at 11023.46,2064.31 h60
  text "DRILLING:" at 9922.46,1925.82 h60
  text "REFERENCE:" at 9997.23,1808.82 h60
  text "X" at 10645.46,1808.82 h60
  text "AS SHOWN" at 10832.46,1808.82 h60
  text "X" at 11546.46,1808.82 h60
  text "NC_DRILL FILES" at 11683.46,1808.82 h60
  text "PTH MIN COPPER THICKNESS:" at 9997.23,1650.82 h60
  text "X" at 11347.46,1650.82 h60
  text "1MIL" at 11484.46,1650.82 h60
  text "OTHER" at 11981.46,1650.82 h60
  text "BOARD FINISH:" at 9922.46,1491.82 h60
  text "SILKSCREEN:" at 10077.69,1373.82 h60
  text "X" at 11026.46,1373.82 h60
  text "TOP" at 11152.46,1373.82 h60
  text "X" at 11536.46,1373.82 h60
  text "BOTTOM" at 11663.46,1373.82 h60
  text "SILKSCREEN COLOR:" at 10077.69,1206.82 h60
  text "X" at 11025.42,1206.82 h60
  text "WHITE" at 11152.46,1206.82 h60
  text "OTHER" at 11663.46,1206.82 h60
  text "SOLDER RESIST COLOR:" at 10077.69,1036.82 h60
  text "X" at 10645.43,877.62 h60
  text "GREEN" at 10772.46,877.62 h60
  text "BLUE" at 11363.46,877.62 h60
  text "OTHER" at 11901.46,877.62 h60
  text "IMMERSION GOLD (ENIG)" at 10983.46,689.1 h60
  text "ENEPIG" at 12321.01,685.82 h60
  text "SURFACE FINISH:" at 9922.46,684.82 h60
  text "X" at 10796.52,684.82 h60
  text "IMM. TIN/SILVER OR EQUIV" at 10252.01,527.82 h60
  text "OTHER" at 11683.46,527.82 h60
  text "ARRAY/PANEL:" at 9922.46,348.82 h60
  text "CUT AND TRIM PER MECH LAYER 1" at 10983.47,344.53 h60
  text "N.C. ROUTE" at 10983.46,192.82 h60
  text "X" at 11662.46,192.82 h60
  text "V. SCORE" at 11849.46,192.82 h60
  text "CERTIFICATION:" at 9922.46,55.82 h60
  text "MATERIALS AND WORKMANSHIP FOR ALL PCBS" at 10647.46,55.82 h60
  text "TO MEET OR EXCEED THE REQUIREMENTS OF:" at 10647.46,-42.18 h60
  text "X" at 10273.97,-178.69 h60
  text "ANSI IPC-A-600F CLASS ->" at 10412.97,-178.69 h60
  text "X" at 12052.02,-178.69 h60
  text "2" at 12170.97,-178.69 h60
  text "1" at 11855.97,-180.18 h60
  text "3" at 12524.97,-180.18 h60
  text "X" at 10276.02,-338.18 h60
  text "UL 94V-0" at 10412.97,-338.18 h60
  text "X" at 11088.02,-338.18 h60
  text "RoHS" at 11224.97,-338.18 h60
  text "OTHER" at 11869.37,-338.18 h60
  text "PER ORDER" at 12266.43,-338.18 h60
  text "ADDITIONAL REQUIREMENTS:" at 9922.46,-479.18 h60
  text "MICROSECTION:" at 9997.23,-594.18 h60
  text "YES" at 10902.97,-594.18 h60
  text "REQUIRED" at 11764.46,-750.33 h60
  text "BARE BOARD ELEC. TEST:" at 9997.23,-753.18 h60
  text "NONE" at 11302.97,-753.18 h60
  text "X" at 11637.46,-753.18 h60
  text "PER ORDER" at 12356.46,-753.18 h60
  text "MANUFACTURER'S UL:" at 9997.23,-910.18 h60
  text "RAIL" at 11162.97,-914.47 h60
  text "METAL" at 11654.78,-914.47 h60
  text "X" at 12030.01,-914.82 h60
  text "SILK" at 12166.46,-914.47 h60
  text ".Layer_Name" at -832.99,-2723.31 h60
